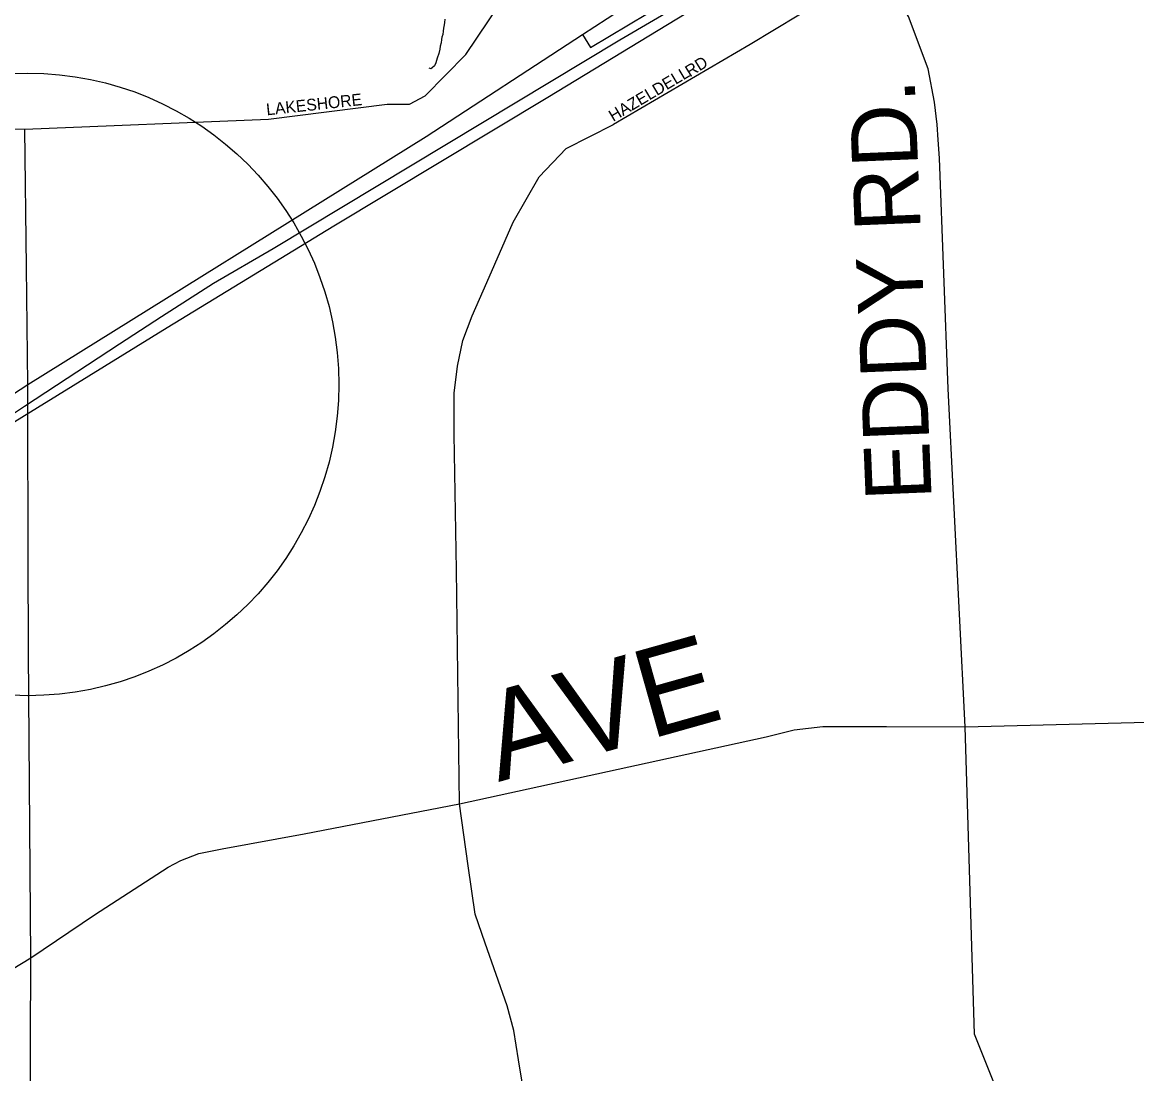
# Model space of a CAD drawing. Extents: x 2139079 to 2262683, y 1235796 to 1334992.
# Drawn here: x 2210756 to 2215487, y 1289914 to 1294375 of the extents above; entities that cross this region are included whole.
import ezdxf

# ---------------------------------------------------------------- set-up
doc = ezdxf.new("R2010")
doc.units = 0
for name, color, linetype in [('GM_X_City_Street', 7, 'Continuous'), ('GM_X_City_Street_Text', 7, 'Continuous'), ('GM_X_Interchange_Ramps', 7, 'Continuous'), ('GM_X_Interstate_Route', 7, 'Continuous'), ('GM_X_Minor_River', 7, 'Continuous'), ('GM_X_Rail_Line', 7, 'Continuous'), ('SH_Text', 7, 'Continuous')]:
    doc.layers.add(name, color=color, linetype=linetype)

msp = doc.modelspace()

# ---------------------------------------------------------------- linework, layer by layer
at = {"layer": 'GM_X_City_Street'}
for points in [[(2210765.7, 1293921.8), (2211801.2, 1293964.2), (2212304.8, 1294027), (2212399.2, 1294027), (2212466.8, 1294063.6), (2212638.5, 1294238.9), (2212784.6, 1294454.5), (2212886.8, 1294651.8), (2212956.2, 1294841.7), (2213029.3, 1295050), (2213142.5, 1295274.2), (2213283.1, 1295420.4), (2213573.5, 1295709), (2214317.9, 1296503.1), (2214511.4, 1296741.1), (2214593.2, 1296875), (2214794.1, 1297172.5), (2214853.5, 1297276.5), (2214913.2, 1297522), (2214972.6, 1297722.9), (2215173.4, 1297923.7), (2216341.1, 1298964.8), (2217218.8, 1299790.1), (2218141.2, 1300729.6)], [(2214644.6, 1293875.9), (2214639.6, 1293941.7), (2214628.6, 1294036), (2214601.9, 1294178), (2214518.7, 1294400), (2214429.8, 1294543.9), (2214203.9, 1294848.4)], [(2213265.1, 1293941.8), (2213266.3, 1293942.4), (2213845.7, 1294282), (2214053.1, 1294406.7), (2214060.3, 1294410.5)], [(2214425, 1291386.3), (2214758.6, 1291385.5), (2215696.7, 1291409.9), (2217535.5, 1292829.9), (2217702.6, 1292941.4), (2217828, 1293024.9), (2217967.3, 1293178.1), (2218190.2, 1293414.8), (2218589.4, 1293842.4), (2218775.3, 1294041.4), (2219027.8, 1294314.4), (2219083.6, 1294374.8)], [(2210524.9, 1293923.8), (2210765.7, 1293921.8)], [(2210772.7, 1293335.8), (2210765.7, 1293921.8)], [(2212588.8, 1292699.5), (2212588.8, 1292801.2), (2212602.9, 1292915.8), (2212626.2, 1293025), (2212665.2, 1293129.4), (2212727.6, 1293271.3), (2212839.8, 1293526.7), (2212950.5, 1293720), (2213065.2, 1293839.5), (2213265.1, 1293941.8)], [(2216494.8, 1287416.7), (2216479.3, 1287435.1), (2216349.9, 1287588), (2215663.4, 1288402.4), (2215307.3, 1288835), (2215053.1, 1289445.6), (2214798.9, 1290081.7), (2214758.6, 1291385.5), (2214686.7, 1292820.2), (2214650.5, 1293799.2), (2214644.6, 1293875.9)], [(2210778.9, 1292749.9), (2210778.7, 1292838.5), (2210772.7, 1293335.8)], [(2210780.7, 1292110.6), (2210778.9, 1292749.9)], [(2212611.7, 1291058.6), (2212599.7, 1292051.3), (2212588.8, 1292626.6), (2212588.8, 1292699.5)], [(2210791.9, 1290405.9), (2210781.9, 1291701.8), (2210780.7, 1292110.6)], [(2206637.8, 1287887.1), (2206870.7, 1288028.3), (2207250.4, 1288258.5), (2210791.9, 1290405.9), (2211061.9, 1290587.5), (2211375.2, 1290789.8), (2211429.3, 1290818.3), (2211504.8, 1290848.2), (2211604.5, 1290868.2), (2211952.5, 1290931.9), (2212611.7, 1291058.6), (2213914.1, 1291343.2), (2214033.3, 1291373.4), (2214154, 1291387), (2214425, 1291386.3)], [(2214858, 1284717.3), (2214826.9, 1284791.1), (2214763.8, 1284874.6), (2214386.6, 1285275), (2214123.6, 1285667.7), (2213516.5, 1286568.1), (2213411.7, 1286739.3), (2213384.7, 1286866.2), (2213315.3, 1287251.5), (2212862.6, 1289972.6), (2212842.7, 1290096.5), (2212814.2, 1290201.9), (2212720.2, 1290466.9), (2212678.8, 1290590.8), (2212648.2, 1290795.3), (2212611.7, 1291058.6)], [(2210780.6, 1287483.9), (2210780.5, 1287493.3), (2210791.9, 1290405.9)]]:
    msp.add_lwpolyline(points, dxfattribs=at)
at = {"layer": 'GM_X_Interchange_Ramps'}
msp.add_lwpolyline([(2213134.5, 1294323.1), (2213168.7, 1294267.8), (2213571, 1294509.8), (2214156.8, 1294877.8), (2214173, 1294890.1)], dxfattribs=at)
at = {"layer": 'GM_X_Interstate_Route'}
for points in [[(2209268.7, 1291750.6), (2210765.4, 1292746), (2211168.5, 1293011), (2211346.1, 1293126.4), (2211567.6, 1293268.1), (2211821.2, 1293415.9), (2213292.4, 1294301), (2213595.9, 1294479.3), (2214194.6, 1294863.9), (2214129.9, 1294963.8), (2214905.3, 1295458), (2215003.2, 1295329.9), (2217276.8, 1296701.3)], [(2207701.2, 1290838), (2207916.4, 1290971.4), (2210778.7, 1292838.5), (2212470.3, 1293891), (2213134.5, 1294323.1), (2213343.6, 1294459.2), (2214118.6, 1294963.4), (2214122.3, 1294965.7)]]:
    msp.add_lwpolyline(points, dxfattribs=at)
at = {"layer": 'GM_X_Minor_River'}
msp.add_lwpolyline([(2212549.8, 1294388.1), (2212548.1, 1294374.1), (2212546.3, 1294364), (2212544.5, 1294349.9), (2212542.8, 1294337.8), (2212541.1, 1294323.7), (2212537.3, 1294311.6), (2212535.5, 1294301.5), (2212533.8, 1294287.4), (2212530, 1294273.2), (2212528.3, 1294261.1), (2212524.6, 1294243), (2212517, 1294222.8), (2212511.4, 1294202.6), (2212505.6, 1294190.4), (2212495.8, 1294182.1), (2212489.8, 1294178), (2212483.8, 1294179.9)], dxfattribs=at)
at = {"layer": 'GM_X_Rail_Line'}
msp.add_lwpolyline([(2203228.1, 1287651), (2204195.4, 1288303.3), (2204797, 1288709.8), (2205631.8, 1289275), (2206337, 1289750.9), (2206850, 1290098.6), (2207481.5, 1290525.3), (2207991.6, 1290871.6), (2208474.1, 1291197), (2209455.6, 1291861.2), (2209862.1, 1292136), (2210353.6, 1292453.2), (2211370.1, 1293079.5), (2212078.2, 1293511.4), (2212986.7, 1294057.2), (2214201.7, 1294795.7), (2216244.5, 1296039.8), (2216686.9, 1296308.3), (2217205.9, 1296624.7), (2218314.7, 1297298.6)], dxfattribs=at)
at = {"layer": 'SH_Text'}
msp.add_circle((2210778.7, 1292838.5), 1321, dxfattribs=at)

# ---------------------------------------------------------------- texts
at = {"layer": 'GM_X_City_Street_Text'}
for s, height, rotation, p in [('RD', 50, 32.0127, (2213589.9, 1294140.9)), ('HAZELDELL', 50, 30.719, (2213264.5, 1293951.8)), ('LAKESHORE', 50, 6.1878, (2211794, 1293980)), ('AVE', 375, 15.7219, (2212776.8, 1291151))]:
    msp.add_text(s, height=height, rotation=rotation, dxfattribs=at).set_placement(p)
at = {"layer": 'GM_X_Interchange_Ramps'}
msp.add_text('EDDY RD.', height=280, rotation=92.3288, dxfattribs=at).set_placement((2214616.9, 1292350.3))

doc.saveas('drawing.dxf')
